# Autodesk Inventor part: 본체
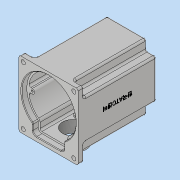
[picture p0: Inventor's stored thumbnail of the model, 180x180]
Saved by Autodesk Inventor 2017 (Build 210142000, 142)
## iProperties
Part Number: 본체
Material: 일반
Document SubType Name: Modeling
Designer: MRC
Density: 1 g/cm^3
Appearance: 기본값
Mass: 520.076 g
Surface Area: 1170.75 cm^2
Volume: 520.076 cm^3
Author: MRC
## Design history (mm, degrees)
sketch "스케치1"
  geometry: L1 (49, 55)-(-49, 55); L2 (-49, 55)-(-49, -55); L3 (-49, -55)-(49, -55); L4 (49, -55)-(49, 55); L5 (49, 55)-(-49, -55); L6 (-49, 55)-(49, -55); 1 further point
  constraints: 12 end point, 2 midpoint, 2 parallel, 1 horizontal, 1 perpendicular
  dimensions: "d0" = 98 distance of L3.end L2.end; "d1" = 110 distance of L2.end L1.end
extrude "돌출1" new body sketch "스케치1" distance "d2" = 10; taper "d3" = 0 deg
fillet "모깎기1" dims "d4" = 3
sketch "스케치2"
  geometry: L1 (46, 55)-(-46, 55) reference; L2 (33, -55)-(-33, -55); L3 (-33, -55)-(-33, 55); L4 (-33, 55)-(33, 55); L5 (33, 55)-(33, -55); L6 (33, -55)-(-33, 55); L7 (-33, -55)-(33, 55); 1 further point
  constraints: 12 end point, 2 midpoint, 2 parallel, 1 horizontal, 1 perpendicular, 1 point on line
  dimensions: "d5" = 66 distance of L3.end L4.end
extrude "돌출2" join sketch "스케치2" distance "d6" = 120; taper "d7" = 0 deg
sketch "스케치3"
  geometry: L1 (-49, -38)-(49, -38); L2 (49, -38)-(49, 28); L3 (49, 28)-(-49, 28); L4 (-49, 28)-(-49, -38); L5 (-49, -38)-(49, 28); L6 (49, -38)-(-49, 28); L7 (46, 55)-(-46, 55) reference; 3 further points
  constraints: 12 end point, 3 midpoint, 2 parallel, 1 horizontal, 1 perpendicular, 1 vertical alignment
  dimensions: "d8" = 98 distance of L3.end L2.end; "d9" = 66 distance of L2.end L1.end; "d10" = 27 distance between parallel lines of L7 L3
extrude "돌출3" join sketch "스케치3" distance "d11" = 120; taper "d12" = 0 deg
fillet "모깎기2" dims "d13" = 3
fillet "모깎기3" dims "d14" = 3
fillet "모깎기4" dims "d15" = 3
fillet "모깎기5" dims "d16" = 3
sketch "스케치4"
  geometry: L1 (-49, -41)-(-49, -52) reference; L2 (-46, -55)-(-36, -55) reference; C1 r 3.5 at (-42, -48); C2 r 3.5 at (-42, 48); C3 r 3.5 at (42, 48); C4 r 3.5 at (42, -48); 1 further point
  constraints: 4 centre point, 2 horizontal alignment, 2 vertical alignment
  dimensions: "d17" = 7 diameter of C1; "d18" = 7 diameter of C2; "d19" = 7 diameter of C3; "d20" = 7 diameter of C4; "d21" = 7 distance from line of L1 C1.centre; "d22" = 7 distance from line of L2 C1.centre; "d23" = 84 distance of C4.centre C1.centre; "d24" = 96 distance of C1.centre C2.centre
extrude "돌출4" cut sketch "스케치4" distance "d25" = 120; taper "d26" = 0 deg
sketch "스케치5"
  geometry: L1 (-27, -21)-(27, -21); L2 (27, -21)-(27, 33); L3 (27, 33)-(-27, 33); L4 (-27, 33)-(-27, -21); L5 (-27, -21)-(27, 33); L6 (27, -21)-(-27, 33); L7 (-30, -55)-(30, -55) reference; 3 further points
  constraints: 12 end point, 3 midpoint, 2 parallel, 1 horizontal, 1 perpendicular, 1 vertical alignment
  dimensions: "d27" = 54 distance of L3.end L2.end; "d28" = 54 distance of L2.end L1.end; "d29" = 61 distance from line of L7 point (0, 6)
extrude "돌출5" join sketch "스케치5" distance "d30" = 7; taper "d31" = 0 deg
fillet "모깎기6" dims "d32" = 3
fillet "모깎기7" dims "d33" = 3
sketch "스케치6"
  geometry: L1 (-46, 55)-(46, 55) reference; L2 (-23, -33.249)-(-23, -42); L3 (-20, -45)-(20, -45); L4 (23, -42)-(23, -33.249); L5 (0, 0)-(0, -65.918); A1 r 42 centre (0, 5) between (25.375, -28.468) and (-25.375, -28.468); A2 r 6 centre (29, -33.249) between (25.375, -28.468) and (23, -33.249); A3 r 6 centre (-29, -33.249) between (-23, -33.249) and (-25.375, -28.468); A4 r 3 centre (20, -42) between (20, -45) and (23, -42); A5 r 3 centre (-20, -42) between (-23, -42) and (-20, -45); 4 further points
  constraints: 12 point on circle, 8 end point, 8 tangent, 6 point on line, 5 centre point, 2 equal radius, 2 perpendicular, 2 vertical, 1 vertical alignment, 1 other
  dimensions: "d34" = 84 diameter of A1; "d35" = 50 distance from line of L1 A1.centre; "d36" = 46 distance of point (-23, -45) point (23, -45); "d37" = 50 distance from line of A1.centre L3; "d38" = 6 radius of A2; "d39" = 3 radius of A4
extrude "돌출6" cut sketch "스케치6" distance "d40" = 121; taper "d41" = 0 deg
sketch "스케치7"
  geometry: L1 (-23, -42)-(-23, -33.249) reference; L2 (20, -45)-(-20, -45) reference; L3 (23, -33.249)-(23, -42) reference; L4 (-26, -42)-(-26, -33.249); L5 (26, -33.249)-(26, -42); L6 (20, -48)-(-20, -48); A1 r 6 centre (29, -33.249) between (25.375, -28.468) and (23, -33.249) reference; A2 r 42 centre (0, 5) between (25.375, -28.468) and (-25.375, -28.468) reference; A3 r 6 centre (-29, -33.249) between (-23, -33.249) and (-25.375, -28.468) reference; A4 r 3 centre (-20, -42) between (-23, -42) and (-20, -45) reference; A5 r 3 centre (20, -42) between (20, -45) and (23, -42) reference; A6 r 6 centre (-20, -42) between (-26, -42) and (-20, -48); A7 r 3 centre (-29, -33.249) between (-26, -33.249) and (-27.188, -30.859); A8 r 45 centre (0, 5) between (27.188, -30.859) and (-27.188, -30.859); A9 r 3 centre (29, -33.249) between (27.188, -30.859) and (26, -33.249); A10 r 6 centre (20, -42) between (20, -48) and (26, -42); 1 further point
  constraints: 10 point on circle, 6 end point, 5 centre point, 7 other
  dimensions: "d42" = 3 distance between parallel lines of L2 L6
extrude "돌출7" cut sketch "스케치7" distance "d43" = 9; taper "d44" = 0 deg
chamfer "모따기1" distance "d45" = 1; stored, may be unused: second distance "d46" = 2, angle "d47" = 45 deg
sketch "스케치8"
  geometry: L1 (-46, 55)-(46, 55) reference; L2 (35.778, 1.006)-(41.81, 1.006); L3 (35.778, 8.994)-(41.81, 8.994); A1 r 36 centre (0, 5) between (36, 5) and (35.778, 1.006); A2 r 42 centre (0, 5) between (25.375, -28.468) and (-25.375, -28.468) reference; A3 r 4 centre (36, 5) between (36.222, 8.994) and (36.222, 1.006); 1 further point
  constraints: 9 point on circle, 4 end point, 2 centre point, 2 horizontal, 2 point on line, 1 horizontal alignment, 1 vertical alignment
  dimensions: "d48" = 72 diameter of A1; "d49" = 50 distance from line of L1 A1.centre; "d50" = 8 diameter of A3
extrude "돌출8" join sketch "스케치8" distance "d51" = 112; taper "d52" = 0 deg
fillet "모깎기8" dims "d53" = 3
fillet "모깎기9" dims "d54" = 3
sketch "스케치9"
  geometry: A1 r 4 centre (36, 5) between (35.778, 8.994) and (35.778, 1.006) reference; 2 further points
  constraints: 1 coincident
hole "구멍1" sketch "스케치9" at (36, 5) diameter "d55" = 3.242; stored, may be unused: countersink angle "d59" = 90 deg, drill point angle "d61" = 118 deg; dims "d56" = 7, "d57" = 4, "d58" = 2, "d60" = 9
sketch "스케치10"
  geometry: L1 (-46, 55)-(46, 55) reference; A1 r 21 centre (0, -6) between (-12.163, 11.119) and (12.163, 11.119); A2 r 15 centre (0, 25) between (11.584, 15.47) and (-11.584, 15.47); A3 r 3 centre (13.901, 13.565) between (11.584, 15.47) and (12.163, 11.119); A4 r 3 centre (-13.901, 13.565) between (-12.163, 11.119) and (-11.584, 15.47); 1 further point
  constraints: 8 point on circle, 4 centre point, 4 tangent, 2 vertical alignment, 1 equal radius
  dimensions: "d62" = 42 diameter of A1; "d63" = 61 distance from line of L1 A1.centre; "d64" = 30 diameter of A2; "d65" = 30 distance from line of L1 A2.centre; "d66" = 3 radius of A3 (derived)
extrude "돌출9" join sketch "스케치10" distance "d67" = 7; taper "d68" = 0 deg
fillet "모깎기10" dims "d69" = 3
sketch "스케치11"
  geometry: C1 r 17.5 at (0, -6); A1 r 21 centre (0, -6) between (-12.163, 11.119) and (12.163, 11.119) reference; 1 further point
  constraints: 1 centre point, 1 coincident
  dimensions: "d70" = 35 diameter of C1
extrude "돌출10" cut sketch "스케치11" distance "d71" = 10; taper "d72" = 0 deg
sketch "스케치12"
  geometry: A1 r 15 centre (0, 25) between (11.584, 15.47) and (-11.584, 15.47) reference; 2 further points
  constraints: 1 coincident
hole "구멍2" sketch "스케치12" at (0, 25) diameter "d73" = 19; stored, may be unused: countersink angle "d77" = 90 deg, drill point angle "d79" = 0 deg; dims "d74" = 7, "d75" = 22, "d76" = 7, "d78" = 10
fillet "모깎기11" dims "d80" = 3
fillet "모깎기12" dims "d81" = 0.3
chamfer "모따기2" distance "d82" = 1; stored, may be unused: second distance "d83" = 2, angle "d84" = 45 deg
sketch "스케치13"
  geometry: L1 (-27, 30)-(-27, -18) reference; L2 (24, 33)-(-24, 33) reference; C1 r 14 at (0, 6); 3 further points
  constraints: 2 midpoint, 1 centre point, 1 horizontal alignment, 1 vertical alignment
  dimensions: "d85" = 28 diameter of C1
extrude "돌출11" cut sketch "스케치13" stored distance "d86" = 10; taper "d87" = 0 deg
sketch "스케치14"
  geometry: C1 r 14 at (0, 6) reference; C2 r 16 at (0, 6); 1 further point
  constraints: 1 centre point, 1 coincident
  dimensions: "d88" = 32 diameter of C2
extrude "돌출12" cut sketch "스케치14" distance "d89" = 8.3; taper "d90" = 0 deg
fillet "모깎기13" dims "d91" = 0.3
chamfer "모따기3" distance "d92" = 0.8; stored, may be unused: second distance "d93" = 2, angle "d94" = 30 deg
sketch "스케치15"
  geometry: L1 (0, 0)-(92, 0) reference; C1 r 15 at (46, 89); 2 further points
  constraints: 1 centre point, 1 midpoint, 1 vertical alignment
  dimensions: "d95" = 30 diameter of C1; "d96" = 89 distance from line of L1 C1.centre
extrude "돌출13" join sketch "스케치15" distance "d97" = 5; taper "d98" = 0 deg
sketch "스케치16"
  geometry: L1 (0, 0)-(92, 0) reference; C1 r 22.5 at (46, 40); 2 further points
  constraints: 1 centre point, 1 midpoint, 1 vertical alignment
  dimensions: "d99" = 45 diameter of C1; "d100" = 40 distance from line of L1 C1.centre
extrude "돌출14" join sketch "스케치16" distance "d101" = 10; taper "d102" = 0 deg
fillet "모깎기14" dims "d103" = 3
sketch "스케치18"
  geometry: C1 r 15 at (20, 80) reference; C2 r 15 at (20, 80); 1 further point
  constraints: 1 centre point, 1 coincident
  dimensions: "d104" = 30 diameter of C2
extrude "돌출15" cut sketch "스케치18" distance "d105" = 5; taper "d106" = 0 deg
chamfer "모따기4" distance "d107" = 1; stored, may be unused: second distance "d108" = 2, angle "d109" = 30 deg
sketch "스케치20"
  geometry: C1 r 15 at (0, 0) reference; C2 r 10 at (0, 0); 1 further point
  constraints: 1 centre point, 1 coincident
  dimensions: "d110" = 20 diameter of C2
extrude "돌출16" cut sketch "스케치20" stored distance "d111" = 5; taper "d112" = 0 deg
sketch "스케치21"
  geometry: C1 r 22.5 at (0, 0) reference; 2 further points
  constraints: 1 coincident
hole "구멍3" sketch "스케치21" at (0, 0) diameter "d113" = 33.376; stored, may be unused: countersink angle "d117" = 90 deg, drill point angle "d119" = 0 deg; dims "d114" = 70, "d115" = 32, "d116" = 7, "d118" = 77.3
sketch "스케치22"
  geometry: L1 (104, 130)-(83, 130) reference; L2 (80, 13)-(80, 127) reference; 2 further points
  constraints: 1 other
  dimensions: "d120" = 65 distance from line of L1 point (47, 65); "d121" = 33 distance from line of L2 point (47, 65)
feature "엠보싱1" sketch "스케치22" dims "d5" = 66, "d122" = 0.5, "d123" = 0
chamfer "모따기5" distance "d124" = 1; stored, may be unused: second distance "d125" = 2, angle "d126" = 45 deg
node "솔리드1"
mirror "미러1"
mirror "미러2"
node "투영된 루프1"
